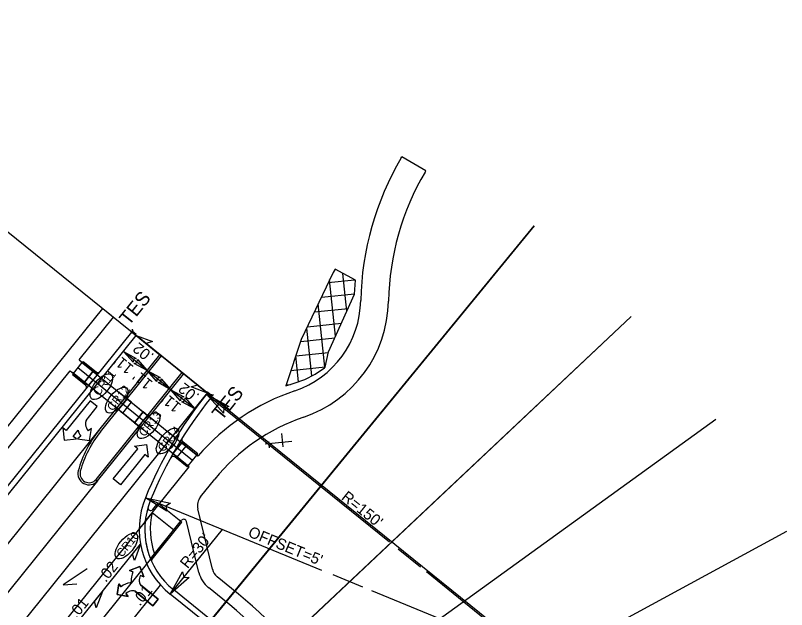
# Model space of a CAD drawing. Extents: x 1486489 to 1490134, y 497089 to 500876.
# Drawn here: x 1488844.3 to 1489121.9, y 499231.7 to 499445.5 of the extents above; entities that cross this region are included whole.
import ezdxf

# ---------------------------------------------------------------- set-up
doc = ezdxf.new("R2010")
doc.units = 0
for name, color, linetype in [('DEV PRELIMINARY STAMP CELL', 7, 'Continuous'), ('Gray Area Fill Shapes', 7, 'Continuous'), ('Pattern 5', 7, 'Continuous'), ('Prop Guardrail', 7, 'Continuous'), ('Prop Guardrail Anchor Unit CELL', 7, 'Continuous'), ('Prop Horizontal Alignment Station Label', 7, 'Continuous'), ('Prop North Arrow NAD83 for Plan Sheets CELL', 7, 'Continuous'), ('Prop Rem of Exist Asph Pvmt', 7, 'Continuous'), ('Prop Text', 7, 'Continuous'), ('Prop WCC CELL', 7, 'Continuous'), ('Scratch_Level_0', 7, 'Continuous'), ('Scratch_Level_5', 7, 'Continuous'), ('Sheet Block Revision CELL', 7, 'Continuous'), ('Sheet Block Title CELL', 7, 'Continuous'), ('Sheet Border Standard 30in CELL', 7, 'Continuous'), ('Sheet Cutting Line CELL', 7, 'Continuous'), ('Sheet Data Field CELL', 7, 'Continuous'), ('Sheet Plan CELL', 7, 'Continuous'), ('Sheet Plot Border Inside CELL', 7, 'Continuous'), ('Sheet Plot Border Outside CELL', 7, 'Continuous'), ('Sheet Sticker Exception Certification CELL', 7, 'Continuous'), ('Sheet Title CELL', 7, 'Continuous')]:
    doc.layers.add(name, color=color, linetype=linetype)

msp = doc.modelspace()

# ---------------------------------------------------------------- linework, layer by layer
at = {"layer": 'DEV PRELIMINARY STAMP CELL'}
msp.add_line((1488913.47, 499309.59), (1488887.78, 499330.31), dxfattribs=at)
for points in [[(1488887.78, 499330.31), (1488893.7, 499328.1), (1488891.38, 499327.41)], [(1488913.47, 499309.59), (1488907.54, 499311.8), (1488909.87, 499312.5)], [(1488889.33, 499255.21), (1488887.12, 499249.29), (1488886.43, 499251.61)], [(1488875.62, 499238.22), (1488873.41, 499232.29), (1488872.72, 499234.62)]]:
    msp.add_lwpolyline(points, close=True, dxfattribs=at)
at = {"layer": 'Gray Area Fill Shapes'}
msp.add_line((1488861.18, 499220.32), (1488889.33, 499255.21), dxfattribs=at)
at = {"layer": 'Pattern 5'}
for p, q in [((1488872.25, 499317.42), (1488869.11, 499313.53)), ((1488870.66, 499312.27), (1488873.8, 499316.17)), ((1488873.8, 499316.17), (1488872.25, 499317.42)), ((1488869.11, 499313.53), (1488870.66, 499312.27)), ((1488884.5, 499307.53), (1488881.37, 499303.64)), ((1488882.92, 499302.38), (1488886.06, 499306.28)), ((1488886.06, 499306.28), (1488884.5, 499307.53)), ((1488881.37, 499303.64), (1488882.92, 499302.38)), ((1488890.34, 499302.82), (1488887.2, 499298.93)), ((1488891.9, 499301.57), (1488890.34, 499302.82)), ((1488888.76, 499297.68), (1488891.9, 499301.57)), ((1488887.2, 499298.93), (1488888.76, 499297.68)), ((1488904.16, 499291.68), (1488901.02, 499287.79)), ((1488905.72, 499290.43), (1488904.16, 499291.68)), ((1488902.58, 499286.53), (1488905.72, 499290.43)), ((1488901.02, 499287.79), (1488902.58, 499286.53)), ((1488893.58, 499266.61), (1488891.01, 499263.42)), ((1488892.95, 499249.9), (1488894.4, 499251.7))]:
    msp.add_line(p, q, dxfattribs=at)
for radius, start, end in [(26, 166.4473, 199.835), (28, 174.0509, 202.2902)]:
    msp.add_arc((1488918.86, 499260.52), radius, start, end, dxfattribs=at)
at = {"layer": 'Prop Guardrail'}
msp.add_line((1488913.24, 499309.78), (1488887.62, 499330.44), dxfattribs=at)
at = {"layer": 'Prop Guardrail Anchor Unit CELL'}
for p, q in [((1488887.62, 499330.44), (1488886.74, 499331.15)), ((1488887.79, 499330.66), (1488886.92, 499331.37)), ((1488887.62, 499330.44), (1488887.79, 499330.66)), ((1488913.24, 499309.78), (1488913.42, 499310)), ((1488913.24, 499309.78), (1488914.12, 499309.07)), ((1488913.42, 499310), (1488914.29, 499309.29))]:
    msp.add_line(p, q, dxfattribs=at)
for centre, radius, start, end in [((1488887.56, 499332.11), 1.27, 159.0507, 229.4447), ((1488887.98, 499332.56), 1.6, 179.9907, 228.2982), ((1488914.88, 499310.08), 1.27, 232.7866, 303.1806), ((1488915.23, 499310.58), 1.6, 233.9331, 282.2406)]:
    msp.add_arc(centre, radius, start, end, dxfattribs=at)
at = {"layer": 'Prop Horizontal Alignment Station Label'}
for p, q in [((1488983.22, 499394.23), (1488983.44, 499394.61)), ((1488992.05, 499389.52), (1488983.44, 499394.61)), ((1488991.83, 499389.14), (1488992.05, 499389.52)), ((1488797.24, 499242.74), (1488875.71, 499340.04)), ((1488875.71, 499340.04), (1488879.61, 499336.9)), ((1488867.19, 499321.5), (1488879.61, 499336.9)), ((1488865.21, 499316.67), (1488868.35, 499320.56)), ((1488867.19, 499321.5), (1488873.8, 499316.17)), ((1488801.14, 499239.6), (1488864.05, 499317.61)), ((1488864.05, 499317.61), (1488870.66, 499312.27)), ((1488869.11, 499313.53), (1488872.25, 499317.42)), ((1488870.66, 499312.27), (1488873.8, 499316.17)), ((1488881.37, 499303.64), (1488884.5, 499307.53)), ((1488882.92, 499302.38), (1488886.06, 499306.28)), ((1488884.5, 499307.53), (1488891.9, 499301.57)), ((1488881.37, 499303.64), (1488888.76, 499297.68)), ((1488887.2, 499298.93), (1488890.34, 499302.82)), ((1488888.76, 499297.68), (1488891.9, 499301.57)), ((1488901.02, 499287.79), (1488904.16, 499291.68)), ((1488910, 499286.97), (1488903.58, 499292.15)), ((1488902.58, 499286.53), (1488905.72, 499290.43)), ((1488906.86, 499283.08), (1488901.02, 499287.79)), ((1488906.47, 499283.39), (1488909.61, 499287.29)), ((1488910, 499286.97), (1488910.04, 499286.95)), ((1488891.01, 499263.42), (1488906.86, 499283.08)), ((1488910.92, 499272.19), (1488916.06, 499278.56)), ((1488896.09, 499269.73), (1488903.88, 499263.45)), ((1488893.58, 499266.61), (1488901.36, 499260.34)), ((1488915.22, 499246.16), (1488909.96, 499267.88)), ((1488892.95, 499249.9), (1488904.15, 499263.79)), ((1488910.36, 499244.98), (1488905.9, 499263.4)), ((1488922.1, 499239.28), (1488916.94, 499243.44)), ((1488918.96, 499235.39), (1488913.8, 499239.55))]:
    msp.add_line(p, q, dxfattribs=at)
for centre, radius, start, end in [((1489073.61, 499340.81), 105, 149.4145, 178.8847), ((1489073.61, 499340.81), 95, 149.4145, 178.8847), ((1488933.64, 499343.53), 35, 288.7222, 358.8847), ((1488933.64, 499343.53), 45, 288.7222, 358.8847), ((1488970.55, 499234.62), 80, 108.7222, 139.1474), ((1488970.55, 499234.62), 70, 108.7222, 141.1156), ((1488914.82, 499269.05), 5, 141.1156, 193.6145), ((1488918.86, 499260.52), 26, 166.4473, 199.835), ((1488904.93, 499263.16), 1, 13.6145, 141.1156), ((1488920.08, 499247.33), 10, 193.6145, 231.1156), ((1488920.08, 499247.33), 5, 193.6145, 231.1156), ((1488796.55, 499083.6), 200, 21.0099, 51.1156), ((1488796.55, 499083.6), 195, 21.0099, 51.1156)]:
    msp.add_arc(centre, radius, start, end, dxfattribs=at)
at = {"layer": 'Prop North Arrow NAD83 for Plan Sheets CELL'}
for p, q in [((1488874.95, 499295.69), (1488896.93, 499322.93)), ((1488896.93, 499322.93), (1488896.34, 499323.4)), ((1488868.35, 499320.56), (1488868.67, 499320.95)), ((1488868.67, 499320.95), (1488873.34, 499317.18)), ((1488865.21, 499316.67), (1488864.9, 499316.28)), ((1488864.9, 499316.28), (1488869.57, 499312.51)), ((1488873.32, 499278.53), (1488904.32, 499316.97)), ((1488904.9, 499316.5), (1488904.32, 499316.97)), ((1488909.92, 499287.68), (1488904.53, 499292.03)), ((1488906.16, 499283.01), (1488901.7, 499286.6)), ((1488909.61, 499287.29), (1488909.92, 499287.68)), ((1488906.47, 499283.39), (1488906.16, 499283.01)), ((1488893.77, 499267.65), (1488895.7, 499270.04)), ((1488896.09, 499269.73), (1488895.7, 499270.04)), ((1488903.88, 499263.45), (1488904.26, 499263.14)), ((1488893.55, 499249.86), (1488904.26, 499263.14))]:
    msp.add_line(p, q, dxfattribs=at)
for centre, radius, start, end in [((1488873.97, 499317.96), 1, 231.1327, 321.1156), ((1488868.94, 499311.73), 1, 321.1156, 51.1156), ((1488905.51, 499271.05), 39.25, 141.1156, 164.6721), ((1488905.16, 499292.8), 1, 148.0494, 231.1156), ((1488901.07, 499285.82), 1, 51.1156, 151.2037), ((1488870.79, 499280.57), 3.25, 164.6721, 321.1156), ((1488892.99, 499268.28), 1, 163.3073, 321.1156), ((1488894.33, 499249.23), 1, 141.1156, 204.7278)]:
    msp.add_arc(centre, radius, start, end, dxfattribs=at)
at = {"layer": 'Prop Rem of Exist Asph Pvmt'}
for p, q in [((1488963.63, 499339.04), (1488962.17, 499352.67)), ((1488956.95, 499349.37), (1488966.36, 499350.38)), ((1488959.57, 499330.06), (1488957.4, 499350.31)), ((1488954.44, 499344.07), (1488966.43, 499345.36)), ((1488955.73, 499318.9), (1488953.3, 499341.65)), ((1488951.93, 499338.78), (1488964.1, 499340.08)), ((1488951.04, 499315.76), (1488949.19, 499333)), ((1488949.42, 499333.48), (1488961.71, 499334.8)), ((1488947, 499328.19), (1488959.32, 499329.51)), ((1488946.24, 499313.65), (1488945.24, 499322.94)), ((1488945.26, 499322.98), (1488956.98, 499324.23)), ((1488943.51, 499317.76), (1488955.8, 499319.08)), ((1488952.16, 499316.35), (1488955.59, 499318.67)), ((1488941.76, 499312.54), (1488943.38, 499312.72)), ((1488940.74, 499290.19), (1488940.21, 499295.08)), ((1488934.2, 499291.29), (1488943.81, 499292.32)), ((1488935.75, 499289.83), (1488935.49, 499292.21))]:
    msp.add_line(p, q, dxfattribs=at)
for points in [[(1488959.38, 499354.2), (1488958.67, 499353), (1488947.21, 499328.81), (1488941.64, 499312.19)], [(1488966.77, 499350.16), (1488959.38, 499354.2)], [(1488966.42, 499345.2), (1488966.77, 499350.16)], [(1488955.77, 499318.96), (1488957.02, 499324.44), (1488966.42, 499345.2)], [(1488955.59, 499318.67), (1488955.77, 499318.96)], [(1488941.64, 499312.19), (1488944.68, 499313.11), (1488948.53, 499314.44), (1488952.16, 499316.35)]]:
    msp.add_lwpolyline(points, dxfattribs=at)
at = {"layer": 'Prop Text'}
for p, q in [((1489031.06, 499369.78), (1488777.53, 499060.39)), ((1488774.7, 499063.04), (1489066.03, 499337.13)), ((1488867.97, 499320.87), (1488910, 499286.97)), ((1488906.86, 499283.08), (1488864.82, 499316.98)), ((1488891.01, 499263.42), (1488849.49, 499211.94)), ((1488898.79, 499257.15), (1488857.27, 499205.66))]:
    msp.add_line(p, q, dxfattribs=at)
at = {"layer": 'Prop WCC CELL'}
for centre in [(1488875.25, 499311.9), (1488880.78, 499307.05), (1488892.23, 499297.83), (1488899.07, 499292.32), (1488884.26, 499254.55)]:
    msp.add_ellipse(centre, major_axis=(3.52, 4.36), ratio=0.462467, dxfattribs=at)
at = {"layer": 'Scratch_Level_0'}
for p, q in [((1488908.04, 499285.34), (1488866.78, 499318.61)), ((1488913.13, 499309.18), (1488979, 499256.05)), ((1488891.1, 499271.9), (1488954.52, 499245.9)), ((1488900.02, 499237.17), (1488918.86, 499260.52)), ((1488982.12, 499253.54), (1488990.19, 499247.03)), ((1488958.58, 499244.24), (1488969.26, 499239.86)), ((1488992.27, 499245.35), (1489029.89, 499215.01)), ((1488972.46, 499238.55), (1489029.89, 499215.01))]:
    msp.add_line(p, q, dxfattribs=at)
for points in [[(1488919.16, 499302.32), (1488913.13, 499309.18), (1488921.18, 499304.74), (1488919.28, 499304.22)], [(1488898.84, 499267.05), (1488891.1, 499271.9), (1488900.08, 499269.95), (1488898.41, 499268.9)], [(1488906.88, 499243.2), (1488900.02, 499237.17), (1488904.46, 499245.22), (1488904.98, 499243.32)]]:
    msp.add_lwpolyline(points, close=True, dxfattribs=at)
at = {"layer": 'Scratch_Level_5'}
for p, q in [((1488794.57, 499217.92), (1488886.22, 499331.56)), ((1488886.22, 499331.56), (1488887.78, 499330.31)), ((1488915.02, 499308.34), (1488913.47, 499309.59)), ((1488914.69, 499307.92), (1488915.02, 499308.34)), ((1488913.62, 499228.77), (1488901.28, 499238.73))]:
    msp.add_line(p, q, dxfattribs=at)
for centre, radius, start, end in [((1489029.89, 499215.01), 148, 141.1156, 157.7135), ((1488918.86, 499260.52), 28, 157.7135, 231.1156)]:
    msp.add_arc(centre, radius, start, end, dxfattribs=at)
at = {"layer": 'Sheet Block Revision CELL'}
msp.add_lwpolyline([(1488870.15, 499246.36), (1488861.53, 499240.6), (1488866.43, 499240.95)], dxfattribs=at)
at = {"layer": 'Sheet Block Title CELL'}
for p, q in [((1488829.46, 499205.43), (1488913.13, 499309.18)), ((1488809.08, 499215.2), (1488874.37, 499296.16)), ((1488873.9, 499278.05), (1488834.73, 499229.48))]:
    msp.add_line(p, q, dxfattribs=at)
at = {"layer": 'Sheet Border Standard 30in CELL'}
for p, q in [((1488777.53, 499060.39), (1489031.06, 499369.78)), ((1489066.03, 499337.13), (1488774.7, 499063.04)), ((1488772.23, 499066.03), (1489096.5, 499300.23)), ((1489121.95, 499259.71), (1488770.16, 499069.32))]:
    msp.add_line(p, q, dxfattribs=at)
at = {"layer": 'Sheet Cutting Line CELL'}
for p, q in [((1488891.73, 499317.69), (1488883.17, 499324.59)), ((1488900.29, 499310.78), (1488891.73, 499317.69)), ((1488908.86, 499303.88), (1488900.29, 499310.78))]:
    msp.add_line(p, q, dxfattribs=at)
at = {"layer": 'Sheet Data Field CELL'}
msp.add_line((1488877.31, 499216.66), (1488896.52, 499240.49), dxfattribs=at)
at = {"layer": 'Sheet Plan CELL'}
msp.add_line((1488744.94, 499445.5), (1489056.31, 499194.4), dxfattribs=at)
at = {"layer": 'Sheet Plot Border Inside CELL'}
for p, q in [((1488871.21, 499306.82), (1488862.55, 499296.07)), ((1488873.78, 499304.75), (1488871.21, 499306.82)), ((1488869.73, 499299.72), (1488873.78, 499304.75)), ((1488862.55, 499296.07), (1488861.38, 499297.02)), ((1488861.38, 499297.02), (1488861.89, 499292.63)), ((1488871.71, 499296.84), (1488870.52, 499296)), ((1488871.01, 499292.47), (1488871.71, 499296.84)), ((1488865.12, 499294), (1488866.91, 499296.22)), ((1488866.29, 499293.06), (1488865.12, 499294)), ((1488867.85, 499294.05), (1488866.63, 499293.17)), ((1488861.89, 499292.63), (1488866.29, 499293.06)), ((1488866.63, 499293.17), (1488871.01, 499292.47)), ((1488879.53, 499278.67), (1488888.32, 499289.57)), ((1488887.15, 499290.51), (1488891.54, 499291.02)), ((1488888.32, 499289.57), (1488887.15, 499290.51)), ((1488891.54, 499291.02), (1488892.06, 499286.56)), ((1488890.89, 499287.5), (1488882.1, 499276.6)), ((1488892.06, 499286.56), (1488890.89, 499287.5)), ((1488882.1, 499276.6), (1488879.53, 499278.67)), ((1488885.39, 499245.68), (1488889.14, 499247.16)), ((1488889.14, 499247.16), (1488890.55, 499243.46)), ((1488886.62, 499245.19), (1488885.39, 499245.68)), ((1488890.55, 499243.46), (1488889.31, 499243.95)), ((1488885.92, 499241.69), (1488885.62, 499241.31)), ((1488880.97, 499237.03), (1488881.59, 499240.98)), ((1488881.59, 499240.98), (1488882.33, 499239.88)), ((1488889.29, 499240.59), (1488895.71, 499235.42)), ((1488884.85, 499236.4), (1488880.97, 499237.03)), ((1488884.11, 499237.5), (1488884.85, 499236.4)), ((1488893.81, 499233.06), (1488887.36, 499238.27)), ((1488895.71, 499235.42), (1488893.81, 499233.06))]:
    msp.add_line(p, q, dxfattribs=at)
for points in [[(1488889.33, 499243.96), (1488890.55, 499243.46), (1488889.14, 499247.16), (1488885.39, 499245.68), (1488886.62, 499245.19)], [(1488885.92, 499241.69), (1488885.62, 499241.31)], [(1488888.89, 499241.88), (1488888.89, 499241.88)], [(1488882.33, 499239.88), (1488881.59, 499240.98), (1488880.97, 499237.03), (1488884.85, 499236.4), (1488884.1, 499237.49)], [(1488886.07, 499238.37), (1488886.07, 499238.37)], [(1488887.35, 499238.27), (1488893.81, 499233.06), (1488895.71, 499235.42), (1488889.3, 499240.58)]]:
    msp.add_lwpolyline(points, dxfattribs=at)
for centre, radius, start, end in [((1488872.04, 499298.69), 2.52, 155.7305, 192.0425), ((1488873.95, 499298.82), 4.43, 188.5524, 219.406), ((1488871.28, 499296.88), 4.43, 188.6462, 219.5248), ((1488892.88, 499242.13), 6.97, 153.9886, 183.684), ((1488892.88, 499242.13), 6.97, 153.9886, 183.684), ((1488892.88, 499242.13), 4, 152.7487, 183.6789), ((1488892.88, 499242.13), 4, 152.7487, 183.6789), ((1488886.66, 499234.42), 6.97, 98.5524, 128.4052), ((1488886.66, 499234.42), 6.97, 98.5524, 128.4052), ((1488891.17, 499241.88), 2.28, 180.1888, 214.9548), ((1488891.17, 499241.88), 2.28, 180.1888, 214.9548), ((1488886.66, 499234.42), 4, 98.5524, 129.7651), ((1488886.66, 499234.42), 4, 98.5524, 129.7651), ((1488886.54, 499236.15), 2.28, 69.0446, 102.0425), ((1488886.54, 499236.15), 2.28, 69.0446, 102.0425)]:
    msp.add_arc(centre, radius, start, end, dxfattribs=at)
at = {"layer": 'Sheet Plot Border Outside CELL'}
for points in [[(1488886.64, 499320.65), (1488883.17, 499324.59), (1488887.8, 499322.04), (1488886.7, 499321.74)], [(1488888.26, 499321.63), (1488891.73, 499317.69), (1488887.1, 499320.24), (1488888.19, 499320.54)], [(1488895.2, 499313.74), (1488891.73, 499317.69), (1488896.36, 499315.14), (1488895.27, 499314.83)], [(1488896.82, 499314.72), (1488900.29, 499310.78), (1488895.66, 499313.33), (1488896.76, 499313.63)], [(1488903.76, 499306.84), (1488900.29, 499310.78), (1488904.92, 499308.23), (1488903.83, 499307.93)], [(1488905.39, 499307.82), (1488908.86, 499303.88), (1488904.23, 499306.43), (1488905.32, 499306.73)]]:
    msp.add_lwpolyline(points, close=True, dxfattribs=at)
at = {"layer": 'Sheet Sticker Exception Certification CELL'}
for p, q in [((1488732.3, 499137.52), (1488887.78, 499330.31)), ((1488887.78, 499330.31), (1488896.34, 499323.4)), ((1488874.37, 499296.16), (1488896.34, 499323.4)), ((1488873.9, 499278.05), (1488904.83, 499316.4)), ((1488904.83, 499316.4), (1488904.9, 499316.5)), ((1488904.9, 499316.5), (1488913.47, 499309.59)), ((1488913.13, 499309.18), (1488913.47, 499309.59)), ((1488912.37, 499227.21), (1488900.02, 499237.17))]:
    msp.add_line(p, q, dxfattribs=at)
for centre, radius, start, end in [((1489029.89, 499215.01), 150, 141.1156, 157.7135), ((1488905.51, 499271.05), 40, 141.1156, 164.6721), ((1488870.79, 499280.57), 4, 164.6721, 321.1156), ((1488918.86, 499260.52), 30, 157.7135, 231.1156)]:
    msp.add_arc(centre, radius, start, end, dxfattribs=at)

# ---------------------------------------------------------------- texts
at = {"layer": 'Gray Area Fill Shapes'}
for s, rotation, p in [('.02', 141.1755, (1488894.46, 499323.37)), ('.02', 141.1755, (1488910.84, 499308.92)), ('.02', 51.1156, (1488876.81, 499241.22)), ('.01', 51.1156, (1488866.27, 499228.15))]:
    msp.add_text(s, height=4, rotation=rotation, dxfattribs=at).set_placement(p)
at = {"layer": 'Prop Guardrail Anchor Unit CELL'}
for p in [(1488885.17, 499333.55), (1488918.54, 499299.4)]:
    msp.add_text('TES', height=5, rotation=51.1156, dxfattribs=at).set_placement(p)
at = {"layer": 'Prop WCC CELL'}
for s, p in [('CR11', (1488874.29, 499308.37)), ('CR12', (1488879.29, 499302.86)), ('CR13', (1488890.75, 499293.63)), ('CR14', (1488897.58, 499288.13)), ('CR10', (1488882.7, 499250.26))]:
    msp.add_text(s, height=3, rotation=51.1156, dxfattribs=at).set_placement(p)
at = {"layer": 'Scratch_Level_0'}
for s, rotation, p in [("R=150'", 321.1156, (1488961.36, 499271.57)), ("OFFSET=5'", 337.7135, (1488927.75, 499258.09)), ("R=30'", 51.1156, (1488906.31, 499246.15))]:
    msp.add_text(s, height=4, rotation=rotation, dxfattribs=at).set_placement(p)
at = {"layer": 'Sheet Data Field CELL'}
msp.add_text('.01', height=4, rotation=49.7378, dxfattribs=at).set_placement((1488889.09, 499232.71))
at = {"layer": 'Sheet Title CELL'}
for p in [(1488887.17, 499319.09), (1488894.01, 499313.54), (1488904.29, 499305.27)]:
    msp.add_text("11'", height=4, rotation=141.1156, dxfattribs=at).set_placement(p)

doc.saveas('drawing.dxf')
